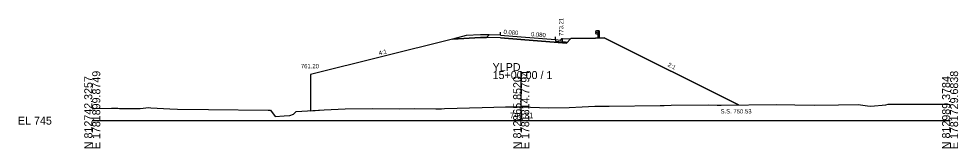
# Model space of a CAD drawing. Extents: x -26 to 353, y -10 to 9080.
# Drawn here: x -25.7 to 302.8, y 4990.3 to 5035.7 of the extents above; entities that cross this region are included whole.
import ezdxf

# ---------------------------------------------------------------- set-up
doc = ezdxf.new("R2010")
doc.units = 0
for name, color, linetype in [('Exist Cross Section Cell', 7, 'Continuous'), ('Exist XS Center Line Elevation Label', 7, 'Continuous'), ('Exist XS Ground Line', 7, 'Continuous'), ('Prop XS Ditch Slope Text', 7, 'Continuous'), ('Prop XS Dump Level', 7, 'Continuous'), ('Prop XS Earthwork Shape', 7, 'Continuous'), ('Prop XS EOT Tick Mark', 7, 'Continuous'), ('Prop XS Finish Grade', 7, 'Continuous'), ('Prop XS Finish Grade CurbGutter', 7, 'Continuous'), ('Prop XS Finish Grade Earthwork', 7, 'Continuous'), ('Prop XS Finish Grade Paved Shoulder', 7, 'Continuous'), ('Prop XS Finish Grade Pavement', 7, 'Continuous'), ('Prop XS Guardrail', 7, 'Continuous'), ('Prop XS Hydro Elevations', 7, 'Continuous'), ('Prop XS Pvmt Edge Slope', 7, 'Continuous'), ('Prop XS SE Text', 7, 'Continuous'), ('Prop XS Side Slope Text', 7, 'Continuous'), ('Prop XS SS Elevation Text', 7, 'Continuous'), ('Prop XS Subgrade CurbGutter', 7, 'Continuous'), ('Prop XS Subgrade Earthwork', 7, 'Continuous'), ('Scratch_Level_3', 7, 'Continuous')]:
    doc.layers.add(name, color=color, linetype=linetype)

msp = doc.modelspace()

# ---------------------------------------------------------------- linework, layer by layer
at = {"layer": 'Exist Cross Section Cell'}
for p, q in [((150, 5000), (150, 5017.39)), ((0, 5000), (150, 5000)), ((150, 5000), (300, 5000))]:
    msp.add_line(p, q, dxfattribs=at)
at = {"layer": 'Exist XS Ground Line'}
for p, q in [((0, 5004.15), (1.05, 5004.24)), ((1.05, 5004.24), (6.75, 5004.41)), ((6.75, 5004.41), (8.96, 5004.32)), ((8.96, 5004.32), (9.58, 5004.29)), ((9.58, 5004.29), (16.77, 5004.28)), ((16.77, 5004.28), (19.77, 5004.56)), ((19.77, 5004.56), (20.53, 5004.53)), ((20.53, 5004.53), (27.15, 5004.18)), ((27.15, 5004.18), (29.76, 5004.03)), ((29.76, 5004.03), (40.63, 5003.94)), ((40.63, 5003.94), (61.49, 5003.67)), ((61.49, 5003.67), (62.31, 5003.65)), ((62.31, 5003.65), (63.95, 5001.48)), ((71.28, 5003.19), (81.07, 5003.78)), ((81.07, 5003.78), (88.49, 5004.14)), ((88.49, 5004.14), (97.92, 5004.24)), ((97.92, 5004.24), (107.28, 5004.14)), ((107.28, 5004.14), (112.77, 5004.2)), ((112.77, 5004.2), (120.15, 5004.18)), ((120.15, 5004.18), (122.17, 5004.19)), ((122.17, 5004.19), (123.21, 5004.21)), ((123.21, 5004.21), (136.34, 5004.66)), ((136.34, 5004.66), (144.51, 5004.83)), ((144.51, 5004.83), (146.78, 5004.83)), ((146.78, 5004.83), (150, 5004.81)), ((150, 5004.81), (159.62, 5004.53)), ((159.62, 5004.53), (166.83, 5004.61)), ((166.83, 5004.61), (171.3, 5004.89)), ((171.3, 5004.89), (175.73, 5005.03)), ((175.73, 5005.03), (180.79, 5005.1)), ((180.79, 5005.1), (198.62, 5005.32)), ((198.62, 5005.32), (199.96, 5005.34)), ((199.96, 5005.34), (202.41, 5005.37)), ((202.41, 5005.37), (215.45, 5005.5)), ((215.45, 5005.5), (218.59, 5005.47)), ((218.59, 5005.47), (219.97, 5005.47)), ((219.97, 5005.47), (239.19, 5005.67)), ((239.19, 5005.67), (245.68, 5005.56)), ((245.68, 5005.56), (252.69, 5005.39)), ((252.69, 5005.39), (261.03, 5005.6)), ((261.03, 5005.6), (267.83, 5005.65)), ((267.83, 5005.65), (271.08, 5005.22)), ((271.08, 5005.22), (272.31, 5005.11)), ((272.31, 5005.11), (277.57, 5005.58)), ((277.57, 5005.58), (278.39, 5005.74)), ((278.39, 5005.74), (292.28, 5005.8)), ((292.28, 5005.8), (297.61, 5005.76)), ((297.61, 5005.76), (300, 5005.68)), ((63.95, 5001.48), (67.06, 5001.64)), ((67.06, 5001.64), (69.15, 5001.75)), ((69.15, 5001.75), (70.38, 5002.31)), ((70.38, 5002.31), (71.28, 5003.19))]:
    msp.add_line(p, q, dxfattribs=at)
at = {"layer": 'Prop XS Dump Level'}
for p, q in [((142.8, 5029.99), (150, 5029.41)), ((150, 5029.41), (162, 5028.45))]:
    msp.add_line(p, q, dxfattribs=at)
at = {"layer": 'Prop XS Earthwork Shape'}
msp.add_lwpolyline([(219.97, 5005.47), (225.95, 5005.53), (179, 5029.01), (176, 5028.95), (167.39, 5028.77), (165.84, 5027.22), (149.93, 5028.5), (142.75, 5029.07), (137.9, 5029.17), (135.82, 5029.21), (125.97, 5028.62), (76.3, 5016.2), (76.3, 5003.49), (81.07, 5003.78), (88.49, 5004.14), (97.92, 5004.24), (107.28, 5004.14), (112.77, 5004.2), (120.15, 5004.18), (122.17, 5004.19), (123.21, 5004.21), (136.34, 5004.66), (144.51, 5004.83), (146.78, 5004.83), (150, 5004.81), (159.62, 5004.53), (166.83, 5004.61), (171.3, 5004.89), (175.73, 5005.03), (180.79, 5005.1), (198.62, 5005.32), (199.96, 5005.34), (202.41, 5005.37), (215.45, 5005.5), (218.59, 5005.47)], close=True, dxfattribs=at)
at = {"layer": 'Prop XS EOT Tick Mark'}
for p, q in [((142.8, 5029.99), (142.8, 5030.99)), ((162, 5028.45), (162, 5029.45))]:
    msp.add_line(p, q, dxfattribs=at)
at = {"layer": 'Prop XS Finish Grade'}
for p, q in [((135.8, 5030.13), (130.8, 5029.83)), ((138.8, 5030.07), (135.8, 5030.13)), ((130.8, 5029.83), (125.97, 5028.62)), ((164.5, 5028.71), (167.39, 5028.77))]:
    msp.add_line(p, q, dxfattribs=at)
at = {"layer": 'Prop XS Finish Grade CurbGutter'}
for p, q in [((162, 5028.45), (163.75, 5028.24)), ((163.75, 5028.24), (163.87, 5028.26)), ((163.87, 5028.26), (163.97, 5028.35)), ((163.97, 5028.35), (164.03, 5028.6)), ((164.03, 5028.6), (164.12, 5028.7)), ((164.25, 5028.71), (164.12, 5028.7)), ((164.5, 5028.71), (164.25, 5028.71))]:
    msp.add_line(p, q, dxfattribs=at)
at = {"layer": 'Prop XS Finish Grade Earthwork'}
for p, q in [((125.97, 5028.62), (76.3, 5016.2)), ((167.39, 5028.77), (176, 5028.95)), ((176, 5028.95), (179, 5029.01)), ((179, 5029.01), (225.95, 5005.53)), ((76.3, 5016.2), (76.3, 5003.49))]:
    msp.add_line(p, q, dxfattribs=at)
at = {"layer": 'Prop XS Finish Grade Paved Shoulder'}
msp.add_line((142.8, 5029.99), (138.8, 5030.07), dxfattribs=at)
at = {"layer": 'Prop XS Finish Grade Pavement'}
for p, q in [((142.8, 5029.99), (150, 5029.41)), ((150, 5029.41), (162, 5028.45))]:
    msp.add_line(p, q, dxfattribs=at)
at = {"layer": 'Prop XS Guardrail'}
for p, q in [((176.03, 5031.33), (176, 5031.27)), ((176, 5031.27), (176.03, 5031.21)), ((176.03, 5030.72), (176, 5030.66)), ((176, 5030.66), (176.03, 5030.6)), ((176.32, 5031.53), (176.03, 5031.33)), ((176.03, 5031.21), (176.32, 5031.01)), ((176.32, 5030.92), (176.03, 5030.72)), ((176.03, 5030.6), (176.32, 5030.4)), ((176.82, 5031.53), (176.32, 5031.53)), ((176.32, 5031.01), (176.32, 5030.92)), ((176.32, 5030.4), (176.82, 5030.4)), ((177.32, 5031.53), (176.82, 5031.53)), ((176.82, 5031.53), (176.82, 5029.03)), ((177.32, 5031.53), (177.32, 5029.03))]:
    msp.add_line(p, q, dxfattribs=at)
at = {"layer": 'Prop XS Pvmt Edge Slope'}
for p, q in [((138.8, 5030.07), (137.9, 5029.17)), ((164.5, 5027.67), (165.5, 5027.59)), ((165.5, 5027.59), (165.84, 5027.22))]:
    msp.add_line(p, q, dxfattribs=at)
at = {"layer": 'Prop XS Subgrade CurbGutter'}
for p, q in [((162, 5028.45), (162, 5027.87)), ((162, 5027.87), (164.5, 5027.67)), ((164.5, 5027.67), (164.5, 5028.71))]:
    msp.add_line(p, q, dxfattribs=at)
at = {"layer": 'Prop XS Subgrade Earthwork'}
for p, q in [((135.82, 5029.21), (125.97, 5028.62)), ((137.9, 5029.17), (135.82, 5029.21)), ((142.75, 5029.07), (137.9, 5029.17)), ((142.75, 5029.07), (149.93, 5028.5)), ((149.93, 5028.5), (165.84, 5027.22)), ((165.84, 5027.22), (167.39, 5028.77))]:
    msp.add_line(p, q, dxfattribs=at)
at = {"layer": 'Scratch_Level_3'}
for p, q in [((135.8, 5030.13), (130.8, 5029.83)), ((138.8, 5030.07), (135.8, 5030.13)), ((137.9, 5029.17), (138.8, 5030.07)), ((130.8, 5029.83), (125.97, 5028.62)), ((125.97, 5028.62), (135.82, 5029.21)), ((135.82, 5029.21), (137.9, 5029.17))]:
    msp.add_line(p, q, dxfattribs=at)

# ---------------------------------------------------------------- texts
at = {"layer": 'Exist Cross Section Cell'}
for s, p in [('YLPD', (140, 5017.39)), ('15+00.00 / 1', (140, 5014.59)), ('EL 745', (-26, 4998.6))]:
    msp.add_text(s, height=2.8, dxfattribs=at).set_placement(p)
for s, p in [('E 1781899.8749', (2.8, 4990)), ('E 1781814.7794', (152.8, 4990)), ('E 1781729.6838', (302.8, 4990)), ('N 812742.3257', (0, 4990)), ('N 812865.8520', (150, 4990)), ('N 812989.3784', (300, 4990))]:
    msp.add_text(s, height=2.8, rotation=90, dxfattribs=at).set_placement(p)
at = {"layer": 'Exist XS Center Line Elevation Label'}
msp.add_text('749.81', height=2, dxfattribs=at).set_placement((146.08, 5000.81))
at = {"layer": 'Prop XS Ditch Slope Text'}
msp.add_text('761.20', height=1.5, dxfattribs=at).set_placement((72.95, 5018.36))
at = {"layer": 'Prop XS Dump Level'}
msp.add_text('Case4', height=0.04, dxfattribs=at).set_placement((130.8, 5029.79))
at = {"layer": 'Prop XS Hydro Elevations'}
msp.add_text('773.21', height=1.5, rotation=90, dxfattribs=at).set_placement((164.75, 5029.71))
at = {"layer": 'Prop XS SE Text'}
for p in [(143.78, 5030.41), (153.38, 5029.64)]:
    msp.add_text('0.080', height=1.5, rotation=355.4261, dxfattribs=at).set_placement(p)
at = {"layer": 'Prop XS Side Slope Text'}
for s, rotation, p in [('4:1', 14.0362, (100.36, 5022.94)), ('2:1', 333.4349, (201.07, 5019.13))]:
    msp.add_text(s, height=1.5, rotation=rotation, dxfattribs=at).set_placement(p)
at = {"layer": 'Prop XS SS Elevation Text'}
msp.add_text('S.S. 750.53', height=1.5, dxfattribs=at).set_placement((219.74, 5002.52))

doc.saveas('drawing.dxf')
